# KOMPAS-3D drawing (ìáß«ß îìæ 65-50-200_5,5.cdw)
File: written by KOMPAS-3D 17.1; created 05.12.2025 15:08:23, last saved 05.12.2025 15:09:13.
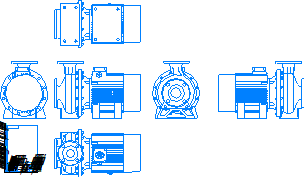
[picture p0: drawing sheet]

Sheet 1: A4, portrait

Title block, sheet 1: name: Насос МНС / 65-50-200_5,5; material: Сталь 10  ГОСТ 1050-88; mass: 165,81; sheets: 1; sheet format: A4

Views: Вид 1, Спереди, Проекционный вид 2, Проекционный вид 3, Проекционный вид 4, Проекционный вид 6
Referenced files in \\adlc.lan\data\АДЛ_ПКД\3D-модели\ADL production\Насосы ГРАНПАМП\Насосы ГРАНПАМП серии МНС\KOMPAS 3D\: Насос МНС 65-50-200_5,5.m3d
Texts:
  Andrey
  АДЛ
Dimensions and other numbers on the sheet: 1:1; 1; 65-50-200_5,5; 165,81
